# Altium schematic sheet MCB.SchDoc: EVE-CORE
size A4; Organization: Ingenia Motion Control; Address1: Carrer Avila, 124, 2B; Address2: 08018 Barcelona Spain; Address3: www.ingeniamc.com; Address4: www.ingeniamc.com; Documentation: https://doc.ingeniamc.com/x/coAZBg
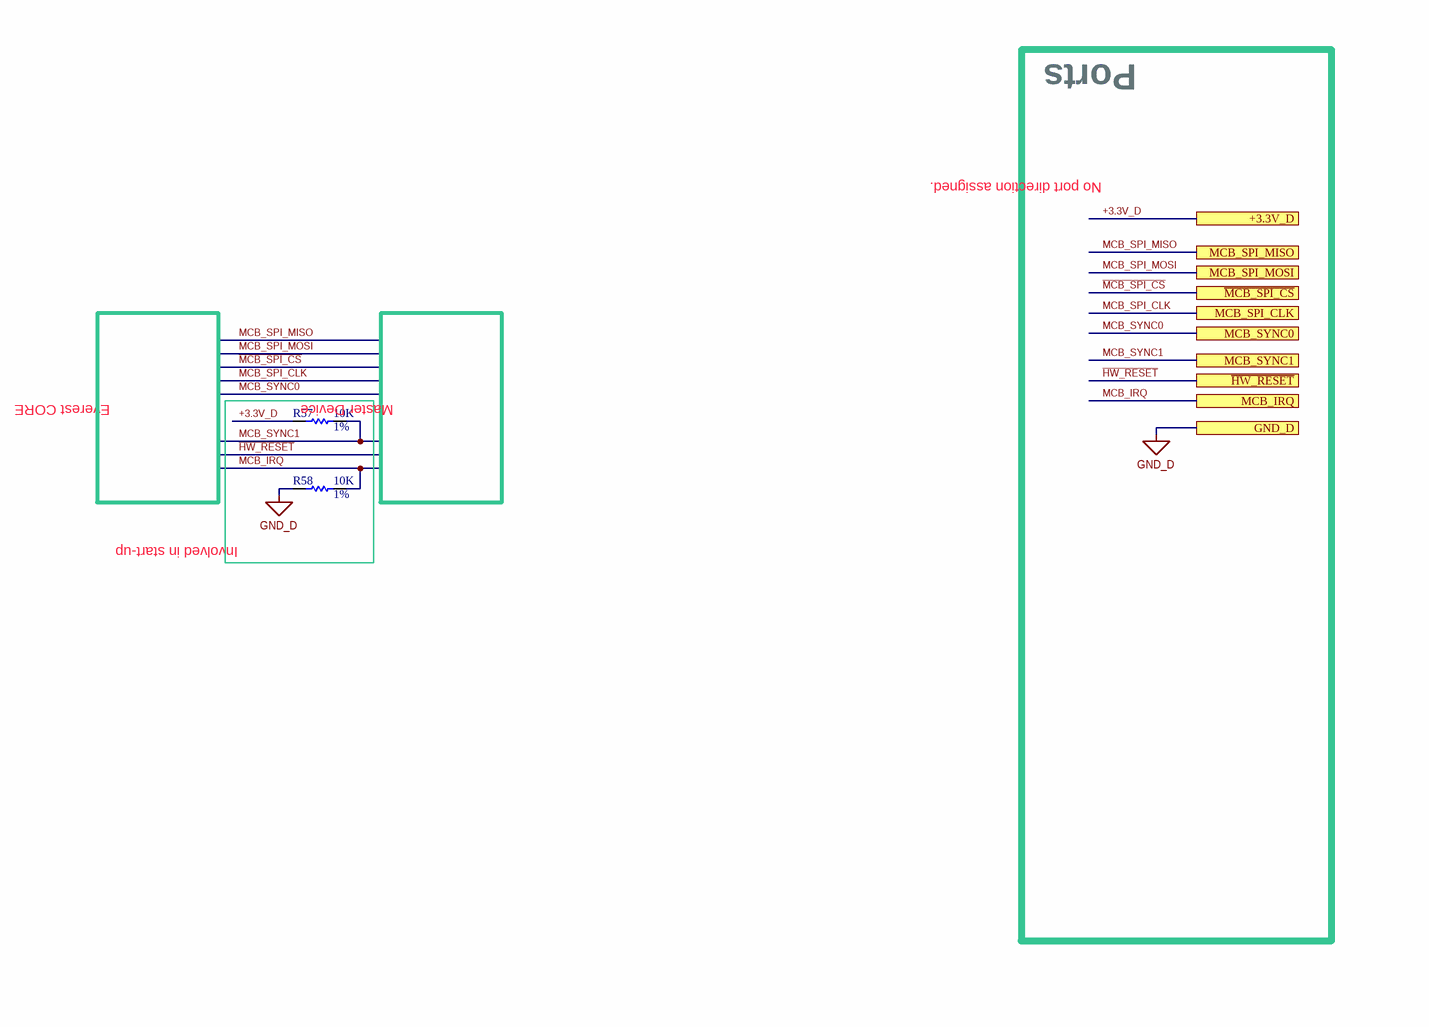
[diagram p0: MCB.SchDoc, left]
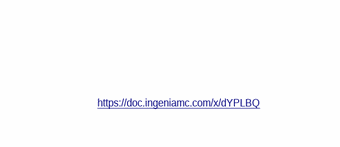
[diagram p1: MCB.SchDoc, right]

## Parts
R57  value 10K  Tolerance: 1%  [R_0402]  (hidden comment: R_0402--10K--1%)
R58  value 10K  Tolerance: 1%  [R_0402]  (hidden comment: R_0402--10K--1%)

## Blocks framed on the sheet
Involved in start-up: R57 R58

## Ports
+3.3V_D, GND_D, MCB_IRQ, MCB_SPI_CLK, MCB_SPI_MISO, MCB_SPI_MOSI, MCB_SYNC0, MCB_SYNC1, ~{HW_RESET}, ~{MCB_SPI_CS}

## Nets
GND_D: R58.1 ; port GND_D
+3.3V_D: R57.1 ; port +3.3V_D
MCB_IRQ: R58.2 ; port MCB_IRQ
MCB_SYNC1: R57.2 ; port MCB_SYNC1

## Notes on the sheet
- Ports
- No port direction assigned.
- Everest CORE
- Master Device
- https://doc.ingeniamc.com/x/dYPLBQ

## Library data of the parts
R57 R58 = R_0402[[/\]]10K[[/\]]1%: RESISTOR 10K OHM 1/16W 1% 0402 SMD; ManufacturerName: Stackpole Electronics; ManufacturerPN: RMCF0402FT10K0; AlternativeManufacturer: Vishay Dale; IsPreferred: 0; IsGeneric: 1; IngeniaID: 685; TemperatureMaxC: 155; TemperatureMinC: -55; MTBF55h: 91649788; AlternativePN: CRCW040210K0FKED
